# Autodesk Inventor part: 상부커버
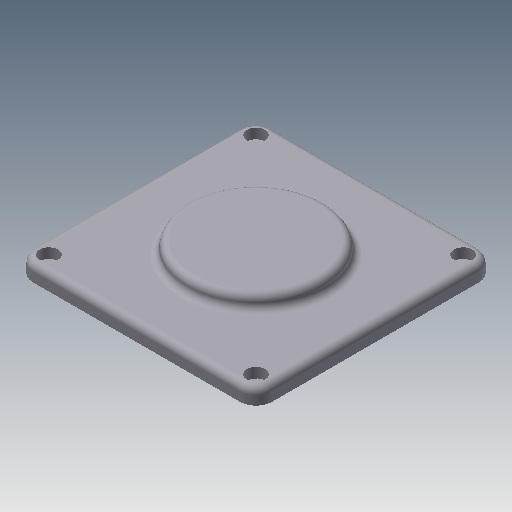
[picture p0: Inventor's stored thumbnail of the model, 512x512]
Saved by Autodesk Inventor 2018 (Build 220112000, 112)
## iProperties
Created: 2018-09
Part Number: 상부커버
Document SubType Name: Modeling
Density: 2.71 g/cm^3
Material: 알루미늄 6061
Mass: 249.405 g
Surface Area: 254.001 cm^2
Volume: 92.0315 cm^3
Appearance: 알루미늄 - 평지
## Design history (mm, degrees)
sketch "스케치5"
  geometry: L1 (-52.5, -52.5)-(52.5, -52.5); L2 (52.5, -52.5)-(52.5, 52.5); L3 (52.5, 52.5)-(-52.5, 52.5); L4 (-52.5, 52.5)-(-52.5, -52.5); L5 (-52.5, -52.5)-(52.5, 52.5); L6 (52.5, -52.5)-(-52.5, 52.5); 1 further point
  constraints: 12 end point, 2 midpoint, 2 parallel, 1 horizontal, 1 perpendicular
  dimensions: "d35" = 105 distance of L3.end L2.end; "d36" = 105 distance of L2.end L1.end
extrude "돌출4" new body sketch "스케치5" distance "d37" = 7; taper "d38" = 0 deg
fillet "모깎기4" dims "d39" = 7
sketch "스케치2"
  geometry: C1 r 30 at (0, 0); 2 further points
  constraints: 2 coincident, 1 centre point
  dimensions: "d4" = 60 diameter of C1
extrude "돌출3" join sketch "스케치2" distance "d5" = 6; taper "d6" = 0 deg
fillet "모깎기1" dims "d7" = 3
sketch "스케치4"
  geometry: L1 (52.5, -45.5)-(52.5, 45.5) reference; L2 (-45.5, -52.5)-(45.5, -52.5) reference; L3 (-52.5, 45.5)-(-52.5, -45.5) reference; L4 (45.5, 52.5)-(-45.5, 52.5) reference; A1 r 7 centre (45.5, 45.5) between (52.5, 45.5) and (45.5, 52.5) reference; A2 r 7 centre (45.5, -45.5) between (45.5, -52.5) and (52.5, -45.5) reference; A3 r 7 centre (-45.5, -45.5) between (-52.5, -45.5) and (-45.5, -52.5) reference; A4 r 7 centre (-45.5, 45.5) between (-45.5, 52.5) and (-52.5, 45.5) reference; 4 further points
  constraints: 4 coincident
hole "구멍3" sketch "스케치4" at (-45.5, 45.5), (-45.5, -45.5), (45.5, -45.5), (45.5, 45.5) diameter "d43" = 4.5; stored, may be unused: countersink angle "d47" = 90 deg, drill point angle "d49" = 118 deg; dims "d44" = 6, "d45" = 8, "d46" = 4.4, "d48" = 8
fillet "모깎기3" dims "d19" = 3
node "솔리드1"
node "솔리드2"
node "투영된 루프2"
